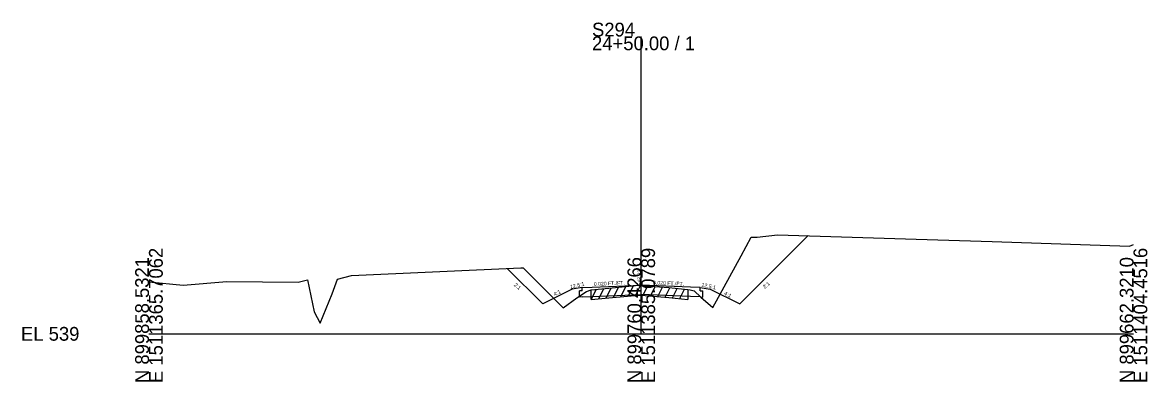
# Model space of a CAD drawing. Extents: x 974 to 2203, y -10 to 19041.
# Drawn here: x 1974.3 to 2202.8, y 8990.3 to 9063.3 of the extents above; entities that cross this region are included whole.
import ezdxf

# ---------------------------------------------------------------- set-up
doc = ezdxf.new("R2010")
doc.units = 0
for name, color, linetype in [('RD_GPK_XS_Cell', 7, 'Continuous'), ('RD_XS_Base', 7, 'Continuous'), ('RD_XS_EarthShd', 7, 'Continuous'), ('RD_XS_ExGround', 7, 'Continuous'), ('RD_XS_ExPaveRet', 7, 'Continuous'), ('RD_XS_Pave', 7, 'Continuous'), ('RD_XS_TX_Elev_EX', 7, 'Continuous'), ('RD_XS_TX_Slope', 7, 'Continuous')]:
    doc.layers.add(name, color=color, linetype=linetype)

msp = doc.modelspace()

# ---------------------------------------------------------------- linework, layer by layer
at = {"layer": 'RD_GPK_XS_Cell'}
for p, q in [((2100, 9000), (2100, 9060.45)), ((2000, 9000), (2100, 9000)), ((2100, 9000), (2200, 9000))]:
    msp.add_line(p, q, dxfattribs=at)
at = {"layer": 'RD_XS_Base'}
for p, q in [((2088, 9008.76), (2087.48, 9008.74)), ((2088, 9008.76), (2088, 9009.4)), ((2112, 9008.76), (2112, 9009.4)), ((2112, 9008.76), (2112.52, 9008.74)), ((2087.48, 9007.47), (2087.48, 9008.74)), ((2087.98, 9007.49), (2087.48, 9007.47)), ((2087.98, 9007.49), (2090, 9007.57)), ((2090, 9007.57), (2100, 9007.97)), ((2110, 9007.57), (2100, 9007.97)), ((2112.02, 9007.49), (2110, 9007.57)), ((2112.02, 9007.49), (2112.52, 9007.47)), ((2112.52, 9007.47), (2112.52, 9008.74))]:
    msp.add_line(p, q, dxfattribs=at)
at = {"layer": 'RD_XS_EarthShd'}
for p, q in [((2120, 9006.07), (2133.89, 9019.96)), ((2080, 9006.07), (2072.76, 9013.3)), ((2086, 9009.07), (2080, 9006.07)), ((2088, 9009.4), (2086, 9009.07)), ((2112, 9009.4), (2114, 9009.07)), ((2114, 9009.07), (2120, 9006.07))]:
    msp.add_line(p, q, dxfattribs=at)
at = {"layer": 'RD_XS_ExGround'}
msp.add_lwpolyline([(2000, 9010.58), (2006.94, 9009.92), (2015.83, 9010.61), (2030.29, 9010.52), (2032.22, 9010.96), (2033.53, 9004.49), (2034.8, 9002.19), (2037.24, 9008.13), (2038.3, 9011.13), (2041.15, 9011.84), (2075.53, 9013.43), (2076.01, 9013.41), (2084.17, 9005.28), (2086.89, 9007.3), (2088.89, 9008.61), (2089.85, 9008.95), (2093.44, 9009.31), (2099.51, 9009.88), (2100, 9009.84), (2105.63, 9009.4), (2109.44, 9009.01), (2109.96, 9008.95), (2110.72, 9008.72), (2112.1, 9007.48), (2114.52, 9005.34), (2120.29, 9015.83), (2122.31, 9019.67), (2123.56, 9019.66), (2127.71, 9020.15), (2155.83, 9019.27), (2171.29, 9018.74), (2199.19, 9017.79), (2200, 9018.15)], dxfattribs=at)
at = {"layer": 'RD_XS_ExPaveRet'}
for p, q in [((2089.85, 9006.95), (2090.91, 9009.06)), ((2089.85, 9006.95), (2089.85, 9008.95)), ((2091.35, 9007.1), (2092.41, 9009.21)), ((2092.85, 9007.25), (2093.91, 9009.36)), ((2094.35, 9007.4), (2095.4, 9009.5)), ((2095.85, 9007.54), (2096.9, 9009.63)), ((2097.35, 9007.68), (2098.4, 9009.77)), ((2098.85, 9007.81), (2099.87, 9009.85)), ((2100.35, 9007.81), (2101.32, 9009.74)), ((2101.85, 9007.69), (2102.82, 9009.62)), ((2103.35, 9007.58), (2104.32, 9009.5)), ((2104.85, 9007.46), (2105.82, 9009.38)), ((2106.35, 9007.33), (2107.31, 9009.23)), ((2107.85, 9007.17), (2108.81, 9009.08)), ((2109.44, 9009.01), (2109.44, 9007.01)), ((2089.85, 9006.95), (2093.44, 9007.31)), ((2093.44, 9007.31), (2099.51, 9007.88)), ((2099.51, 9007.88), (2100, 9007.84)), ((2100, 9007.84), (2105.63, 9007.4)), ((2105.63, 9007.4), (2109.44, 9007.01))]:
    msp.add_line(p, q, dxfattribs=at)
at = {"layer": 'RD_XS_Pave'}
for p, q in [((2088, 9009.4), (2090, 9009.48)), ((2090, 9009.48), (2100, 9009.88)), ((2110, 9009.48), (2100, 9009.88)), ((2112, 9009.4), (2110, 9009.48))]:
    msp.add_line(p, q, dxfattribs=at)

# ---------------------------------------------------------------- texts
at = {"layer": 'RD_GPK_XS_Cell'}
for s, p in [('S294', (2090, 9060.45)), ('24+50.00 / 1', (2090, 9057.65)), ('EL 539', (1974, 8998.6))]:
    msp.add_text(s, height=2.8, dxfattribs=at).set_placement(p)
for s, p in [('E 1511365.7062', (2002.8, 8990)), ('E 1511385.0789', (2102.8, 8990)), ('E 1511404.4516', (2202.8, 8990)), ('N 899858.5321', (2000, 8990)), ('N 899760.4266', (2100, 8990)), ('N 899662.3210', (2200, 8990))]:
    msp.add_text(s, height=2.8, rotation=90, dxfattribs=at).set_placement(p)
at = {"layer": 'RD_XS_TX_Elev_EX'}
msp.add_text('543.92', height=0.75, rotation=90, dxfattribs=at).set_placement((2100, 9009.84))
at = {"layer": 'RD_XS_TX_Slope'}
for s, height, rotation, p in [('2:1', 0.778, 319.3411, (2074.04, 9009.85)), ('4:1', 0.778, 26.3688, (2082.41, 9007.64)), ('12.5:1', 0.778, 12.7511, (2085.61, 9009.15)), ('0.020 FT./FT.', 0.7518, 2.396, (2090.38, 9009.74)), ('0.020 FT./FT.', 0.7518, 357.604, (2102.4, 9010.04)), ('12.5:1', 0.778, 347.2489, (2112.17, 9009.65)), ('2:1', 0.778, 40.6589, (2125.1, 9009.12)), ('4:1', 0.778, 333.6312, (2116.75, 9007.97))]:
    msp.add_text(s, height=height, rotation=rotation, dxfattribs=at).set_placement(p)

doc.saveas('drawing.dxf')
